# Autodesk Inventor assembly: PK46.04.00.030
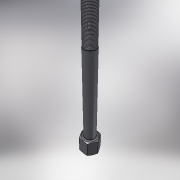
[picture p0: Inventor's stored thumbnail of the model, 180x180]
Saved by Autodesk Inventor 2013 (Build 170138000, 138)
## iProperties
Created: 2005-04
Part Number: PK46.04.00.030
Document SubType Name: Assembly
Designer: salex
Manufacturer: Standard
Standards Organization: Custom
Author: salex
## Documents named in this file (3)
- C:\Product Design Suite 2013 Test Drive\Dynamic Simulation\Workspace\Assy, Chassis, Front\PK46.04.00.030.iam
- C:\Product Design Suite 2013 Test Drive\Dynamic Simulation\Workspace\Assy, Chassis, Front\027.15.22.127.ipt
- C:\Product Design Suite 2013 Test Drive\Dynamic Simulation\Workspace\Assy, Chassis, Front\027.13.14.227.ipt
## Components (2 placed, 2 different names)
1. 027.15.22.127:1 — Вставка:1
2. 027.13.14.227:1 — Вставка:1
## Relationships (1: Insert 1)
- Вставка:1 [Insert]: 027.15.22.127:1 ↔ 027.13.14.227:1
